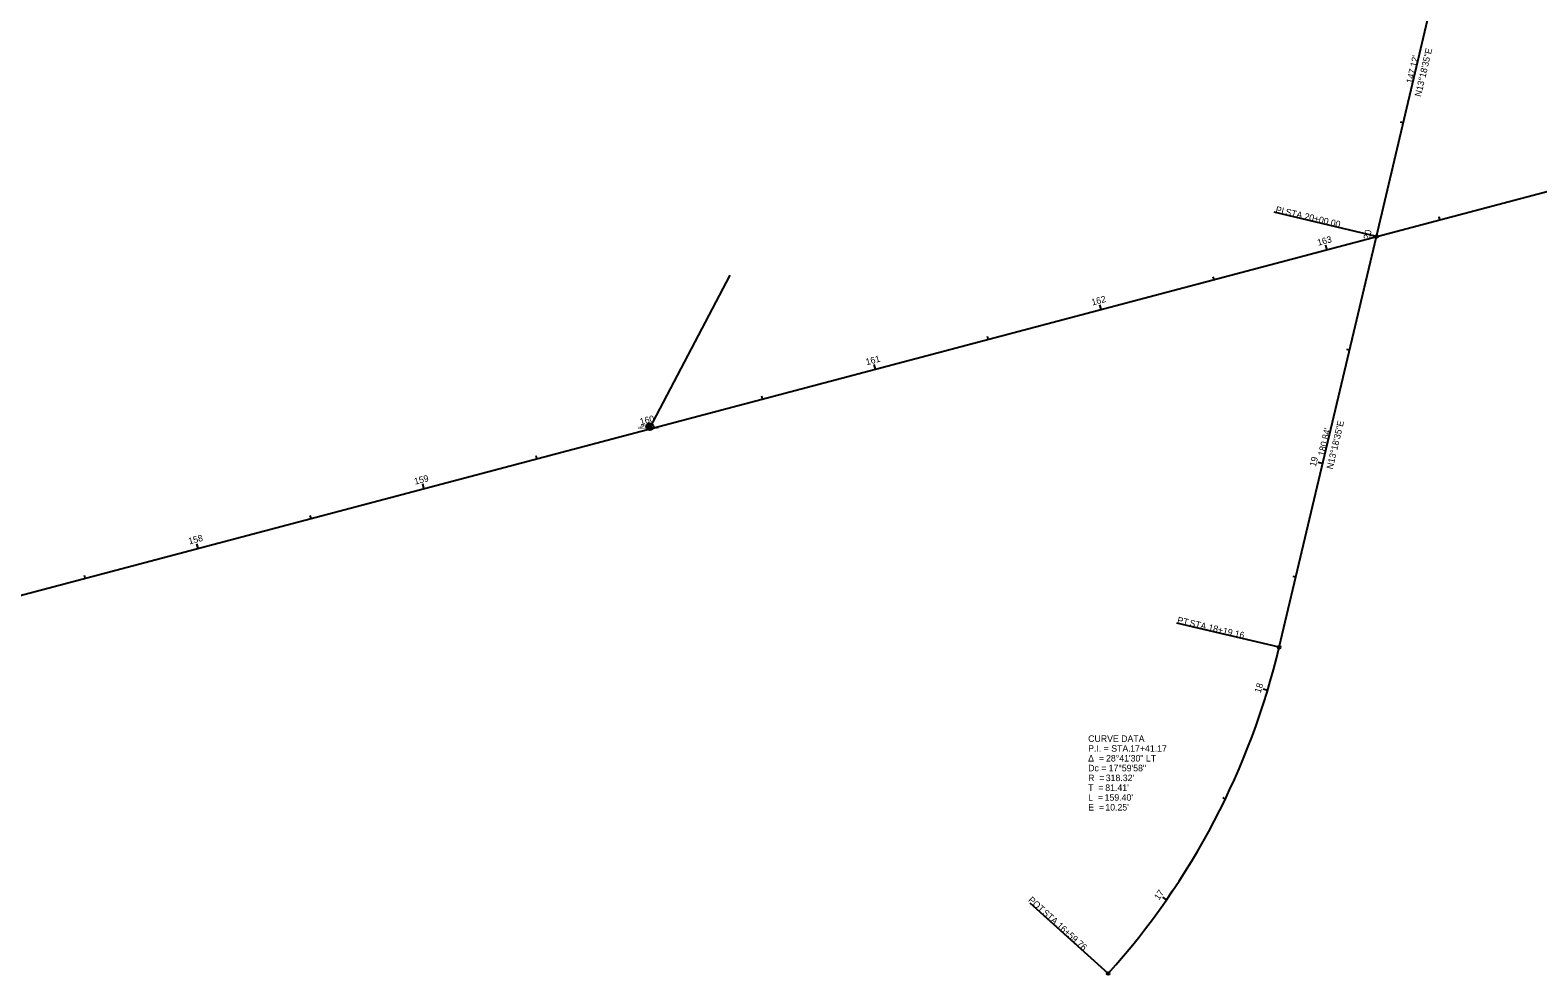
# Model space of a CAD drawing. Extents: x 2124937 to 2129951, y 712967 to 714504.
# Drawn here: x 2127451 to 2128096, y 713632 to 714037 of the extents above; entities that cross this region are included whole.
import ezdxf

# ---------------------------------------------------------------- set-up
doc = ezdxf.new("R2010")
doc.units = 0
for name, color, linetype in [('_CIVIL_CONSTRUCTION', 7, 'Continuous'), ('RW_P_Esmt_TMP', 7, 'Continuous'), ('RW_X_CL', 7, 'Continuous'), ('RW_X_CL_100_Bearings', 7, 'Continuous'), ('RW_X_Esmt_CH', 7, 'Continuous'), ('RW_X_Fee_WL', 7, 'Continuous'), ('SC_Scratch1', 7, 'Continuous'), ('SV_X_Mon_Cells_Found', 7, 'Continuous'), ('SV_X_Text_Comment', 7, 'Continuous'), ('SV_X_Text_Elevation', 7, 'Continuous'), ('SV_X_Text_Name', 7, 'Continuous')]:
    doc.layers.add(name, color=color, linetype=linetype)

msp = doc.modelspace()

# ---------------------------------------------------------------- linework, layer by layer
at = {"layer": '_CIVIL_CONSTRUCTION'}
for p, q in [((2127381.24, 713777.37), (2129950.03, 714457.21)), ((2128027.08, 713948.3), (2128060.94, 714091.46)), ((2127985.44, 713772.31), (2128027.08, 713948.3))]:
    msp.add_line(p, q, dxfattribs=at)
msp.add_arc((2127675.67, 713845.6), 318.32, 317.99857, 346.69024, dxfattribs=at)
at = {"layer": 'RW_P_Esmt_TMP'}
for p, q in [((2128038.59, 713996.95), (2128037.42, 713997.23)), ((2128054.21, 713955.48), (2128053.9, 713956.64)), ((2128027.07, 713948.29), (2128025.13, 713948.75)), ((2128005.88, 713942.69), (2128005.36, 713944.62)), ((2127957.54, 713929.89), (2127957.23, 713931.05)), ((2127909.2, 713917.1), (2127908.69, 713919.03)), ((2127860.87, 713904.31), (2127860.56, 713905.47)), ((2128015.56, 713899.64), (2128014.4, 713899.91)), ((2127812.53, 713891.52), (2127812.02, 713893.45)), ((2127764.2, 713878.72), (2127763.89, 713879.88)), ((2127715.86, 713865.93), (2127715.35, 713867.87)), ((2127667.52, 713853.14), (2127667.22, 713854.3)), ((2128004.05, 713850.98), (2128002.11, 713851.44)), ((2127619.19, 713840.35), (2127618.68, 713842.28)), ((2127570.85, 713827.56), (2127570.54, 713828.72)), ((2127522.52, 713814.76), (2127522, 713816.7)), ((2127474.18, 713801.97), (2127473.87, 713803.13)), ((2127992.54, 713802.32), (2127991.37, 713802.6)), ((2127980.47, 713753.81), (2127978.56, 713754.39)), ((2127962.36, 713707.26), (2127961.28, 713707.78)), ((2127937.19, 713664.12), (2127935.55, 713665.26))]:
    msp.add_line(p, q, dxfattribs=at)
at = {"layer": 'RW_X_Esmt_CH'}
for p, q in [((2128027.08, 713948.3), (2127983.28, 713958.66)), ((2127985.44, 713772.31), (2127941.65, 713782.67)), ((2127912.23, 713632.59), (2127878.79, 713662.7))]:
    msp.add_line(p, q, dxfattribs=at)
for centre in [(2128027.08, 713948.3), (2127985.44, 713772.31), (2127912.23, 713632.59)]:
    msp.add_circle(centre, 0.6, dxfattribs=at)
at = {"layer": 'SC_Scratch1'}
for p, q in [((2127381.24, 713777.37), (2129950.03, 714457.21)), ((2128027.08, 713948.3), (2128060.94, 714091.46)), ((2127985.44, 713772.31), (2128027.08, 713948.3)), ((2127715.86, 713865.93), (2127750.38, 713931.71))]:
    msp.add_line(p, q, dxfattribs=at)
msp.add_arc((2127675.67, 713845.6), 318.32, 317.99857, 346.69024, dxfattribs=at)
at = {"layer": 'SV_X_Text_Name'}
for radius in [1.5, 0.8]:
    msp.add_circle((2127715.95, 713866.84), radius, dxfattribs=at)

# ---------------------------------------------------------------- texts
at = {"layer": 'RW_P_Esmt_TMP'}
for s, rotation, p in [('163', 14.82357, (2128002.14, 713944.28)), ('20', 76.69024, (2128024.15, 713946.78)), ('162', 14.82357, (2127905.46, 713918.7)), ('161', 14.82357, (2127808.78, 713893.11)), ('160', 14.82357, (2127712.06, 713867.51)), ('19', 76.69024, (2128001.14, 713849.5)), ('159', 14.82357, (2127615.43, 713841.94)), ('158', 14.82357, (2127518.74, 713816.35)), ('18', 73.24097, (2127977.46, 713752.49)), ('17', 55.24154, (2127933.93, 713663.79))]:
    msp.add_text(s, height=2.8, rotation=rotation, dxfattribs=at).set_placement(p)
at = {"layer": 'RW_X_CL'}
for p in [(2128046.12, 714007.96), (2128008.37, 713848.38)]:
    msp.add_text('N13°18\'35"E', height=2.8, rotation=76.69024, dxfattribs=at).set_placement(p)
at = {"layer": 'RW_X_CL_100_Bearings'}
msp.add_text('CMON', height=1, dxfattribs=at).set_placement((2127715.95, 713865.84))
at = {"layer": 'RW_X_Esmt_CH'}
for s, rotation, p in [('PI', 346.69024, (2127983.7, 713958.59)), (' STA. ', 346.69024, (2127986.93, 713957.83)), ('20+00.00', 346.69024, (2127996, 713955.68)), ('PT', 346.69024, (2127941.58, 713782.73)), (' STA. ', 346.69024, (2127945.82, 713781.73)), ('18+19.16', 346.69024, (2127954.89, 713779.58)), ('POT', 317.99857, (2127877.72, 713663.72)), (' STA. ', 317.99857, (2127883.02, 713658.94)), ('16+59.76', 317.99857, (2127889.94, 713652.71))]:
    msp.add_text(s, height=2.8, rotation=rotation, dxfattribs=at).set_placement(p)
at = {"layer": 'RW_X_Fee_WL'}
for s, p in [('CURVE DATA', (2127903.64, 713731.78)), ('Δ  = ', (2127903.64, 713723.38)), ('P.I. = STA. ', (2127903.64, 713727.58)), ('28°41\'30" LT', (2127911.29, 713723.38)), ('17+41.17', (2127921.63, 713727.58)), ('Dc = ', (2127903.64, 713719.18)), ('17°59\'58"', (2127912.39, 713719.18)), ('T  = ', (2127903.64, 713710.78)), ('R  = ', (2127903.64, 713714.98)), ("81.41'", (2127910.96, 713710.78)), ("318.32'", (2127911.18, 713714.98)), ('L  = ', (2127903.64, 713706.58)), ("159.40'", (2127910.68, 713706.58)), ('E  = ', (2127903.64, 713702.38)), ("10.25'", (2127910.98, 713702.38))]:
    msp.add_text(s, height=2.8, dxfattribs=at).set_placement(p)
at = {"layer": 'SV_X_Mon_Cells_Found'}
for s, p in [("147.12'", (2128042.51, 714013.62)), ("180.84'", (2128004.74, 713854.05))]:
    msp.add_text(s, height=2.8, rotation=76.69024, dxfattribs=at).set_placement(p)
at = {"layer": 'SV_X_Text_Comment'}
msp.add_text('886.252', height=1, dxfattribs=at).set_placement((2127710.87, 713865.84))
at = {"layer": 'SV_X_Text_Elevation'}
msp.add_text('MN16', height=1, dxfattribs=at).set_placement((2127712.08, 713866.84))

doc.saveas('drawing.dxf')
